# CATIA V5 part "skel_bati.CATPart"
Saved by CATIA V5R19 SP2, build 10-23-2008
Part number: skel_bati
Bounding box of the stored display mesh (mm): x -2 to 18, y 0 to 25.773, z 0 to 10.42
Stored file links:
  E:\TRAVAIL\IAO\skel_bati.CATPart
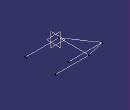
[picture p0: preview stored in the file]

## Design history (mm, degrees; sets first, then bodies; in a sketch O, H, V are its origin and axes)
Body1 (main body)
  Plane1: stored without definition
  Point1 "Point.F": stored without definition
  Point2 "Point.Fprim": stored without definition
  Line1 "axe_pivot_bati_barre4": type Normal, RefPoint Point2, RefSkin Plane1, Start 0, End 20
  Plane2: stored without definition
  Point3 "Point.C": stored without definition
  Point4 "Point.Cprim": stored without definition
  Line2 "axe_pivot_bati_barre5": type Normal, RefPoint Point4, RefSkin Plane2, Start 0, End 20
  Point5 "Point.E": stored without definition
  Point6 "Point.Eprim": stored without definition
  Plane3: stored without definition
  Line3 "axe_pivot_bati_barre1": type Normal, RefPoint Point6, RefSkin Plane3, Start 0, End 20
  Point7 "Point.Fprim": stored without definition
  Point8 "Point.Cprim": stored without definition
  Line4: type PtPt, FirstPoint Point7, SecondPoint Point8
  Point9 "Point.Cprim": stored without definition
  Point10 "Point.Eprim": stored without definition
  Line5: type PtPt, FirstPoint Point9, SecondPoint Point10
  Point11 "Point.Eprim": stored without definition
  Point12 "Point.Fprim": stored without definition
  Line6: type PtPt, FirstPoint Point11, SecondPoint Point12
